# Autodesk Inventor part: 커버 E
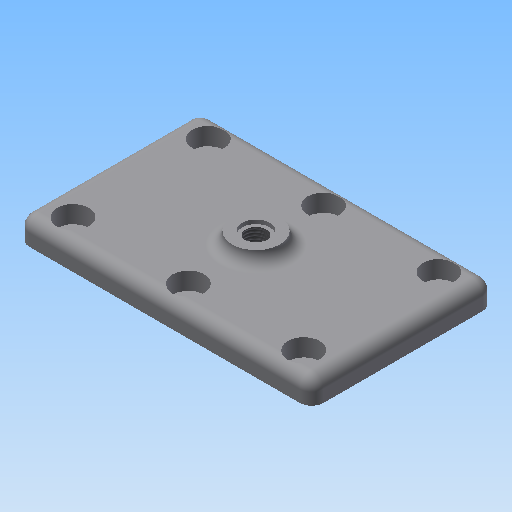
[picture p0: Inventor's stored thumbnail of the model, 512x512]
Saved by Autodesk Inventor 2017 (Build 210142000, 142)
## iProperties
Created: 2020-04
Part Number: 커버 E
Material: 알루미늄 6061
Document SubType Name: Modeling
Designer: mduedu
Density: 1 g/cm^3
Appearance: 기본값
Author: mduedu
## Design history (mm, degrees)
sketch "스케치1"
  geometry: L1 (37, 23)-(-37, 23); L2 (-37, 23)-(-37, -23); L3 (-37, -23)-(37, -23); L4 (37, -23)-(37, 23); L5 (37, 23)-(-37, -23); L6 (-37, 23)-(37, -23); 1 further point
  constraints: 12 end point, 2 midpoint, 2 parallel, 1 horizontal, 1 perpendicular
  dimensions: "d0" = 74 distance of L3.end L2.end; "d1" = 46 distance of L2.end L1.end
extrude "돌출1" new body sketch "스케치1" distance "d2" = 6; taper "d3" = 0 deg
sketch "스케치2"
  geometry: C1 r 6 at (0, 0); 1 further point
  constraints: 1 centre point, 1 coincident
  dimensions: "d4" = 12 diameter of C1
extrude "돌출2" join sketch "스케치2" distance "d5" = 3; taper "d6" = 0 deg
fillet "모깎기1" dims "d7" = 3
fillet "모깎기2" dims "d8" = 3
fillet "모깎기3" dims "d9" = 3
sketch "스케치3"
  geometry: L1 (-30, -13)-(30, -13); L2 (30, -13)-(30, 13); L3 (30, 13)-(-30, 13); L4 (-30, 13)-(-30, -13); L5 (-30, -13)-(30, 13); L6 (30, -13)-(-30, 13); 1 further point
  constraints: 12 end point, 2 midpoint, 2 parallel, 1 horizontal, 1 perpendicular
  dimensions: "d10" = 60 distance of L3.end L2.end; "d11" = 26 distance of L2.end L1.end
extrude "돌출3" join sketch "스케치3" distance "d12" = 2; taper "d13" = 0 deg
fillet "모깎기4" dims "d14" = 3
chamfer "모따기1" distance "d15" = 0.5; stored, may be unused: second distance "d16" = 2, angle "d17" = 45 deg
sketch "스케치4"
  geometry: L1 (-29, -17)-(29, -17); L2 (29, -17)-(29, 17); L3 (29, 17)-(-29, 17); L4 (-29, 17)-(-29, -17); L5 (-29, -17)-(29, 17); L6 (29, -17)-(-29, 17); 7 further points
  constraints: 12 end point, 4 coincident, 4 midpoint, 2 parallel, 1 horizontal, 1 perpendicular
  dimensions: "d18" = 58 distance of L3.end L2.end; "d19" = 34 distance of L2.end L1.end
hole "구멍1" sketch "스케치4" at (-29, 17), (-29, -17), (29, -17), (29, 17), (0, 17), (0, -17) diameter "d20" = 4.5; stored, may be unused: countersink angle "d24" = 90 deg, drill point angle "d26" = 118 deg; dims "d21" = 6, "d22" = 8, "d23" = 4.4, "d25" = 8
hole "구멍2" diameter "d29" = 5.188; stored, may be unused: countersink angle "d33" = 90 deg, drill point angle "d35" = 118 deg; dims "d27" = 10, "d28" = 10, "d30" = 6, "d31" = 8, "d32" = 4.4, "d34" = 8
sketch "스케치5"
  geometry: C1 r 3.5 at (0, 0); 1 further point
  constraints: 1 centre point, 1 coincident
  dimensions: "d36" = 7 diameter of C1
extrude "돌출4" cut sketch "스케치5" distance "d37" = 1; taper "d38" = 0 deg
node "솔리드1"
